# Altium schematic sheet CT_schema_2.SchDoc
size 313 x 185 mm
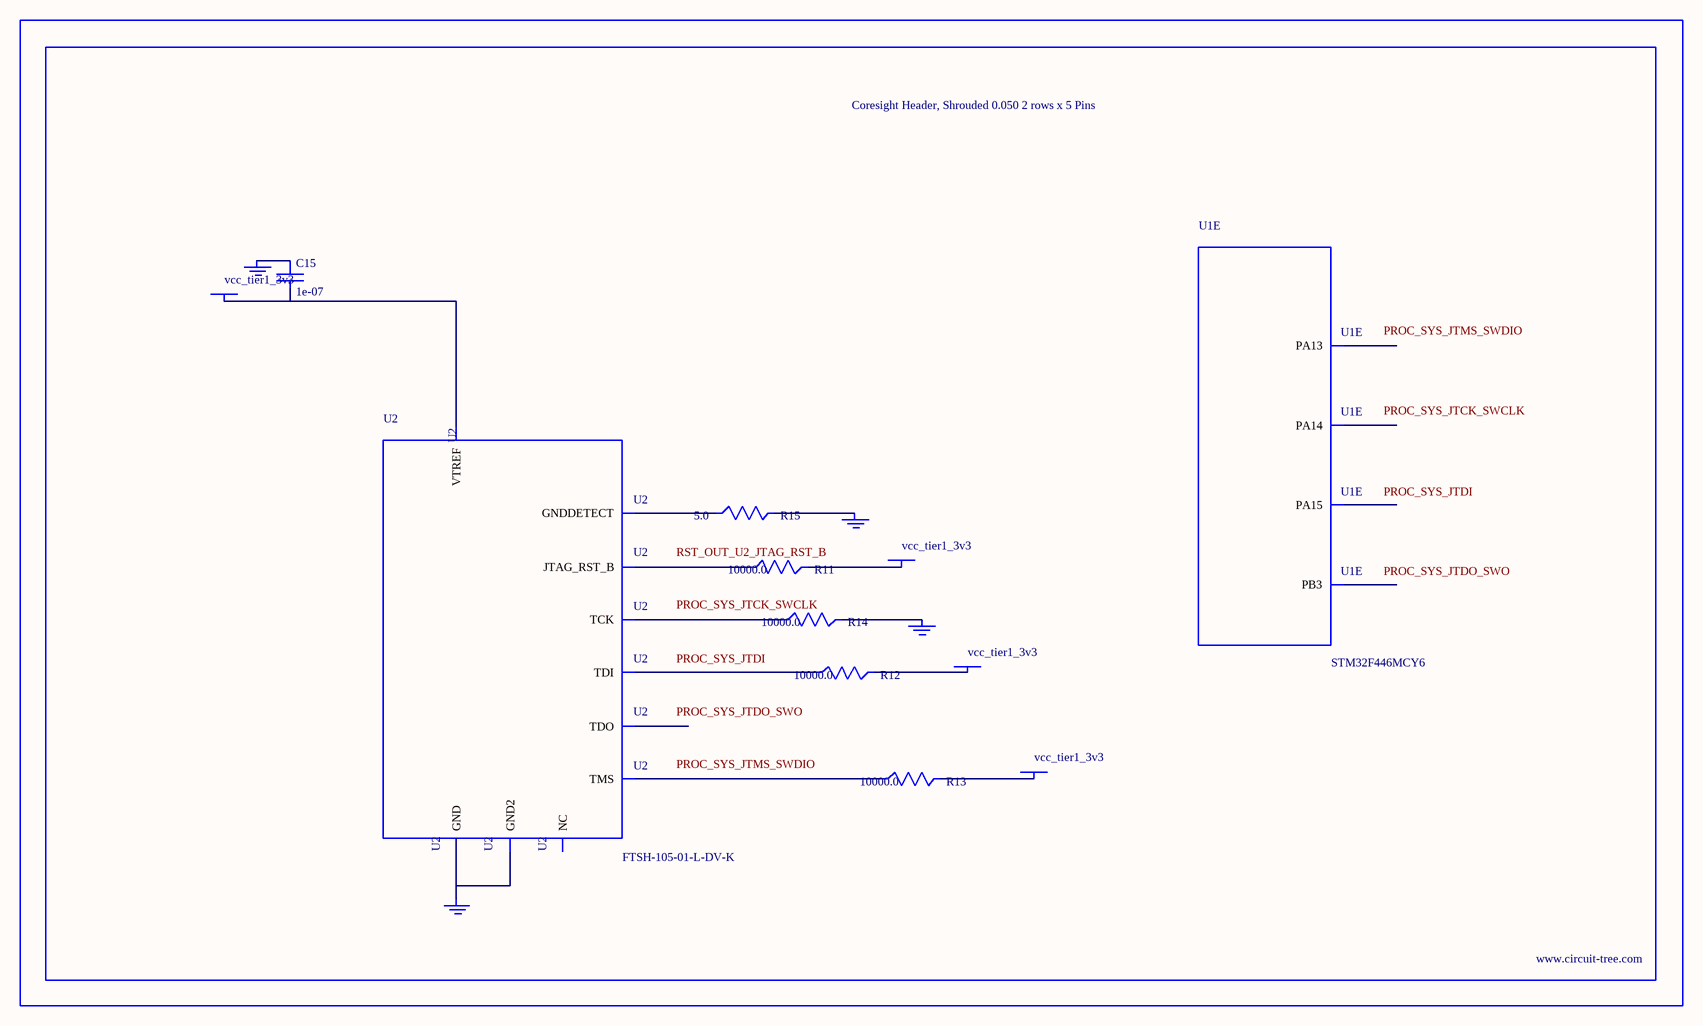
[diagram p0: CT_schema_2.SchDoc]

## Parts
BORDER1  (no value)
C15  1e-07  [C0402]
GND_INSTANCE_1_0  (no value)
GND_INSTANCE_1_1  (no value)
GND_INSTANCE_1_2  (no value)
GND_INSTANCE_1_3  (no value)
POWER_INSTANCE_1_0  vcc_tier1_3v3
POWER_INSTANCE_1_1  vcc_tier1_3v3
POWER_INSTANCE_1_2  vcc_tier1_3v3
POWER_INSTANCE_1_3  vcc_tier1_3v3
R11  10000.0  [R0603]
R12  10000.0  [R0603]
R13  10000.0  [R0603]
R14  10000.0  [R0603]
R15  5.0  [R0603]
U1  STM32F446MCY6  [WLCSP81]  (part E of 9)
U2  FTSH-105-01-L-DV-K  [SAMTEC_FTSH-105-01-L-DV-K]

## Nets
NetC15_1: C15.1 GND_INSTANCE_1_0.0(GND)
NetC15_2: C15.2 POWER_INSTANCE_1_0.0(PWR) U2.1(VTREF)
NetGND_INSTANCE_1_1_0: GND_INSTANCE_1_1.0(GND) R14.2
NetGND_INSTANCE_1_2_0: GND_INSTANCE_1_2.0(GND) R15.2
NetGND_INSTANCE_1_3_0: GND_INSTANCE_1_3.0(GND) U2.3(GND) U2.5(GND2)
NetPOWER_INSTANCE_1_1_0: POWER_INSTANCE_1_1.0(PWR) R13.2
NetPOWER_INSTANCE_1_2_0: POWER_INSTANCE_1_2.0(PWR) R12.2
NetPOWER_INSTANCE_1_3_0: POWER_INSTANCE_1_3.0(PWR) R11.2
NetR11_1: R11.1 U2.10(JTAG_RST_B)
NetR12_1: R12.1 U2.8(TDI)
NetR13_1: R13.1 U2.2(TMS)
NetR14_1: R14.1 U2.4(TCK)
NetR15_1: R15.1 U2.9(GNDDETECT)

Not connected (* = marked no-connect by the designer): U1 A5(PB3) B2(PA15) C3(PA14) D2(PA13); U2 6(TDO) 7(NC)

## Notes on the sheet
- Labels drawn without touching a wire or pin: PROC_SYS_JTCK_SWCLK, PROC_SYS_JTDI, PROC_SYS_JTDO_SWO, PROC_SYS_JTMS_SWDIO, RST_OUT_U2_JTAG_RST_B

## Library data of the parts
BORDER1 = BORDER_PAGE1
C15 = C0402C104K3RACTU
GND_INSTANCE_1_0-GND_INSTANCE_1_3 = GND
POWER_INSTANCE_1_0-POWER_INSTANCE_1_3 = PWR
R11-R14 = RC0603JR-0710KL
R15 = ERJ-3GEYJ5R1V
